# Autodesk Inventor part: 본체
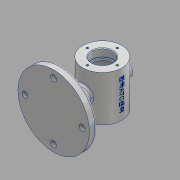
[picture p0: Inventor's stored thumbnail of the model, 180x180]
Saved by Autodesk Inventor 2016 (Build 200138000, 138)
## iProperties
Created: 2018-12
Part Number: 본체
Material: 알루미늄 6061
Document SubType Name: Modeling
Designer: 605-08
Density: 2.7 g/cm^3
Appearance: 알루미늄 - 평지
Mass: 685.082 g
Surface Area: 555.474 cm^2
Volume: 253.734 cm^3
Author: 605-08
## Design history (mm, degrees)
sketch "스케치1"
  geometry: C1 r 55 at (0, 0); 1 further point
  constraints: 1 centre point, 1 coincident
  dimensions: "d0" = 110 diameter of C1
extrude "돌출1" new body sketch "스케치1" distance "d1" = 11; taper "d2" = 0 deg
sketch "스케치3"
  geometry: L1 (75, 35)-(75, -35); L2 (105, 35)-(105, -35); L3 (91, 35)-(91, 23); L4 (91, 23)-(89, 23); L5 (89, 23)-(89, 20); L6 (89, 20)-(100, 20); L7 (100, 20)-(100, -20); L8 (100, -20)-(89, -20); L9 (89, -20)-(89, -23); L10 (89, -23)-(91, -23); L11 (91, -23)-(91, -35); L12 (105, 35)-(91, 35); L13 (105, -35)-(91, -35); 2 further points
  constraints: 26 end point, 7 perpendicular, 4 vertical, 3 horizontal alignment, 2 horizontal, 1 collinear, 1 midpoint, 1 point on line
  dimensions: "d5" = 70 distance of L1.start L1.end; "d6" = 75 distance from line of point (0, 0) L1; "d7" = 60 diameter of L2 L1; "d8" = 32 diameter of L3 L1; "d9" = 28 diameter of L5 L1; "d10" = 12 distance of L3.start L3.end; "d11" = 3 distance of L4.end L5.end; "d12" = 40 distance of L6.end L7.end; "d13" = 3 distance of L8.end L9.end; "d14" = 12 distance of L10.end L11.end; "d15" = 50 diameter of L7 L1
revolve "회전1" sketch "스케치3" stored, may be unused: angle "d16" = 90 deg
sketch "스케치4"
  geometry: L1 (11, -55)-(11, 55) reference; L2 (11, -55)-(22.522, -12); L3 (0, -55)-(11, -55) reference; L4 (0, 0)-(11, 0); L5 (22.522, -12)-(22.522, 0); L6 (22.522, 0)-(11, 0)
  constraints: 8 end point, 1 horizontal, 1 midpoint, 1 vertical
  dimensions: "d17" = 75 deg angle of L3 L2; "d19" = 24 diameter of L2.end L4
revolve "회전2" sketch "스케치4" stored, may be unused: angle "d20" = 90 deg
sketch "스케치5"
  geometry: C1 r 12 at (0, 0); 1 further point
  constraints: 1 centre point, 1 coincident
  dimensions: "d21" = 24 diameter of C1
extrude "돌출2" join sketch "스케치5" stored distance "d22" = 11; taper "d23" = 0 deg
node "작업 평면1"
sketch "스케치6"
  geometry: C1 r 10 at (0, 0); 1 further point
  constraints: 1 centre point, 1 coincident
  dimensions: "d25" = 20 diameter of C1
extrude "돌출3" join sketch "스케치6" stored distance "d26" = 11; taper "d27" = 0 deg
hole "구멍1" diameter "d30" = 10; stored, may be unused: countersink angle "d34" = 90 deg, drill point angle "d36" = 118 deg; dims "d28" = 10, "d29" = 10, "d31" = 6, "d32" = 4, "d33" = 2, "d35" = 8
sketch "스케치7" dims "d37" = 46
  geometry: C1 r 30 at (0, 0) reference; C2 r 16 at (0, 0) reference; 3 further points
  constraints: 2 vertical alignment, 1 coincident, 2 other
hole "구멍2" sketch "스케치7" at (0, 23) diameter "d38" = 3.242; stored, may be unused: countersink angle "d42" = 90 deg, drill point angle "d44" = 118 deg; dims "d39" = 8, "d40" = 4, "d41" = 2, "d43" = 10
sketch "스케치8" dims "d48" = 88
  geometry: 3 further points
  constraints: 2 horizontal alignment, 1 coincident, 2 other
hole "구멍3" sketch "스케치8" at (44, 0) diameter "d49" = 9; stored, may be unused: countersink angle "d53" = 90 deg, drill point angle "d55" = 0 deg; dims "d50" = 8, "d51" = 14, "d52" = 2, "d54" = 10
hole "구멍4" diameter "d58" = 14; stored, may be unused: countersink angle "d62" = 90 deg, drill point angle "d64" = 0 deg; dims "d56" = 10, "d57" = 10, "d59" = 8, "d60" = 14, "d61" = 2, "d63" = 10
sketch "스케치9"
  geometry: L1 (45, 35)-(105, 35) reference; L2 (105, 35)-(105, -35) reference; 2 further points
  constraints: 1 other
  dimensions: "d68" = 35 distance from line of L1 point (75, 0); "d69" = 30 distance from line of L2 point (75, 0)
feature "엠보싱1" sketch "스케치9" dims "d70" = 0.5, "d71" = 0
fillet "모깎기1" dims "d72" = 3
fillet "모깎기2" dims "d73" = 0.3
fillet "모깎기3" dims "d74" = 3
chamfer "모따기1" distance "d75" = 1; stored, may be unused: second distance "d76" = 2, angle "d77" = 45 deg
node "솔리드1"
pattern_circular "원형 패턴1" dims angle "d46" = 360 deg
mirror "대칭1"
pattern_circular "원형 패턴2" dims angle "d66" = 360 deg
node "투영된 루프1"
other parameters: "d3" = 75 deg, "d24" = 112
